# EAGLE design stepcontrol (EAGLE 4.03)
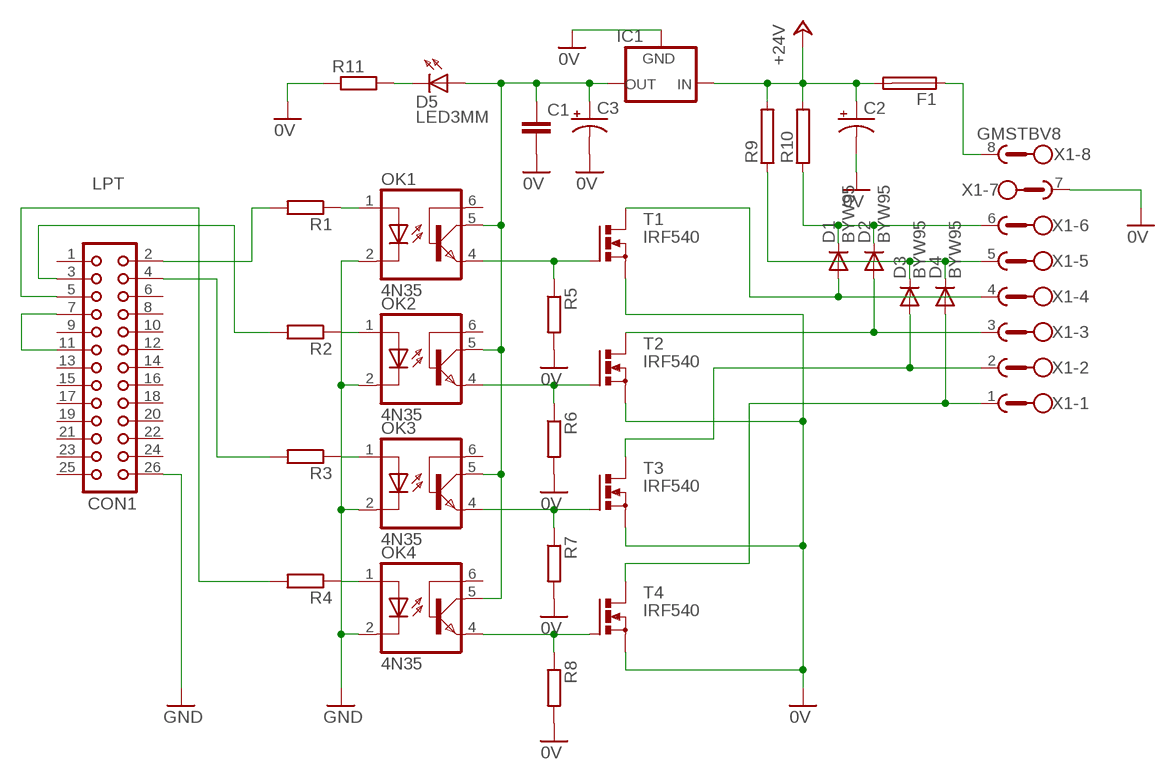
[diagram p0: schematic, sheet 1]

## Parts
C1  C-EU025-025X050  [C025-025X050]
C2  CPOL-USTAP5-50  [TAP5-50]
C3  CPOL-USTAP5-60  [TAP5-60]
CON1  CON26  [CON26]
D1  BYW95  [SOD64-10]
D2  BYW95  [SOD64-10]
D3  BYW95  [SOD64-10]
D4  BYW95  [SOD64-10]
D5  LED3MM  [LED3MM]
F1  GSH15  [GSH15]
IC1  78XXL  [78XXL]
OK1  4N35  [DIL06]
OK2  4N35  [DIL06]
OK3  4N35  [DIL06]
OK4  4N35  [DIL06]
R1  R-EU_0207/12  [0207/12]
R2  R-EU_0207/12  [0207/12]
R3  R-EU_0207/12  [0207/12]
R4  R-EU_0207/12  [0207/12]
R5  R-EU_0207/12  [0207/12]
R6  R-EU_0207/12  [0207/12]
R7  R-EU_0207/12  [0207/12]
R8  R-EU_0207/12  [0207/12]
R9  RKH214-8  [KH214-8]
R10  RKH214-8  [KH214-8]
R11  R-EU_0207/12  [0207/12]
T1  IRF540  [TO220BV]
T2  IRF540  [TO220BV]
T3  IRF540  [TO220BV]
T4  IRF540  [TO220BV]
X1  GMSTBV8  [GMSTBV8]

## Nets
0V [alimentazione]: C1.1 C2.- C3.- IC1.GND R5.2 R6.2 R7.2 R8.2 R11.1 T1.S T2.S T3.S T4.S X1.7
+24V [alimentazione]: C2.+ F1.2 IC1.IN R9.2 R10.2
GND [logic]: CON1.26 OK1.2(C) OK2.2(C) OK3.2(C) OK4.2(C)
N$1: OK4.1(A) R4.1
N$2: OK3.1(A) R3.1
N$3: OK2.1(A) R2.1
N$4: OK1.1(A) R1.1
N$5 [alimentazione]: F1.1 X1.8
N$6 [alimentazione]: D5.K(C) R11.2
N$7 [alimentazione]: D1.C D2.C R10.1 X1.6
N$8 [alimentazione]: D3.C D4.C R9.1 X1.5
N$9 [alimentazione]: D1.A T1.D X1.4
N$10 [logic]: CON1.2 R1.2
N$11 [alimentazione]: D3.A T3.D X1.2
N$12 [alimentazione]: D4.A T4.D X1.1
N$13 [logic]: CON1.3 R2.2
N$14 [alimentazione]: D2.A T2.D X1.3
N$15 [logic]: CON1.4 R3.2
N$16 [logic]: CON1.5 R4.2
N$18 [alimentazione]: OK4.4(EMI) R8.1 T4.G
N$20 [alimentazione]: OK3.4(EMI) R7.1 T3.G
N$22 [alimentazione]: OK2.4(EMI) R6.1 T2.G
N$24 [alimentazione]: OK1.4(EMI) R5.1 T1.G
N$26 [alimentazione]: C1.2 C3.+ D5.A IC1.OUT OK1.5(COL) OK2.5(COL) OK3.5(COL) OK4.5(COL)
N$27 [logic]: CON1.7 CON1.11
Unconnected: CON1.1 CON1.6 CON1.8 CON1.9 CON1.10 CON1.12 CON1.13 CON1.14 CON1.15 CON1.16 CON1.17 CON1.18 CON1.19 CON1.20 CON1.21 CON1.22 CON1.23 CON1.24 CON1.25 OK1.6(BAS) OK2.6(BAS) OK3.6(BAS) OK4.6(BAS)

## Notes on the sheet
- LPT

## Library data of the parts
C1 = rcl:C-EU: CAPACITOR, European symbol
C2 C3 = rcl:CPOL-US: POLARIZED CAPACITOR, American symbol
CON1 = con-harting:CON26: CONNECTOR
D1-D4 = diode:BYW95: DIODE
D5 = led:LED3MM: LED
F1 = fuse:GSH15: FUSE HOLDER
IC1 = v-reg:78XXL: VOLTAGE REGULATOR
OK1-OK4 = optocoupler:4N35: MOTOROLA OPTO COUPLER
R1-R8 R11 = rcl:R-EU_: RESISTOR, European symbol
R9 R10 = resistor-power:R: Power Resitor
T1-T4 = transistor-power:IRF540: N-CHANNEL MOS FET
X1 = con-phoenix-508:GMSTBV8: PHOENIX

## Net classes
1 alimentazione: width 1.016 mm
2 logic: width 0.635 mm

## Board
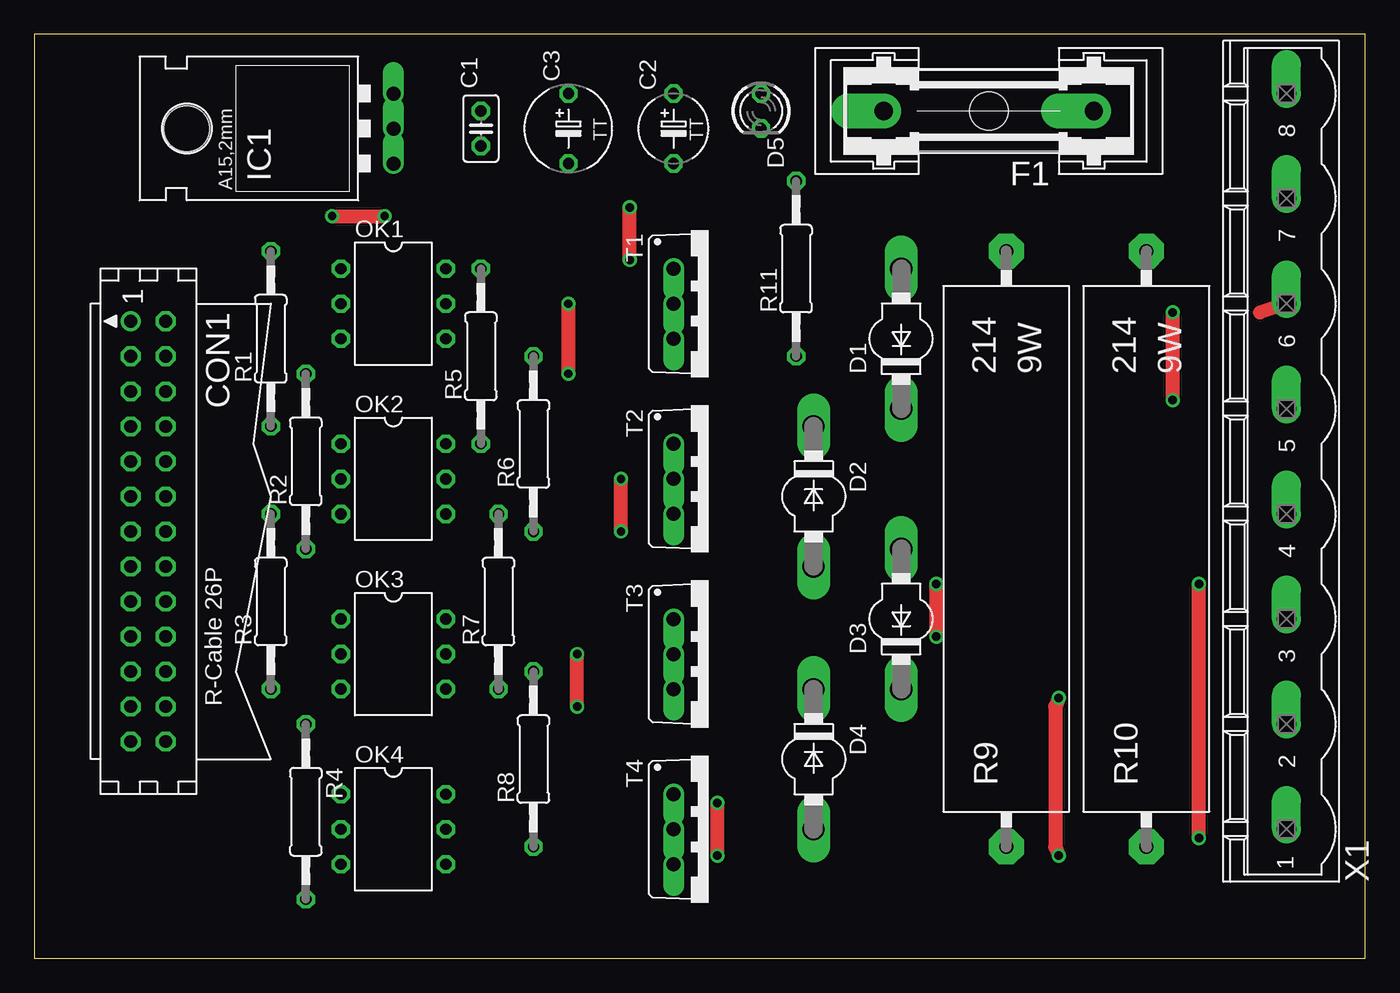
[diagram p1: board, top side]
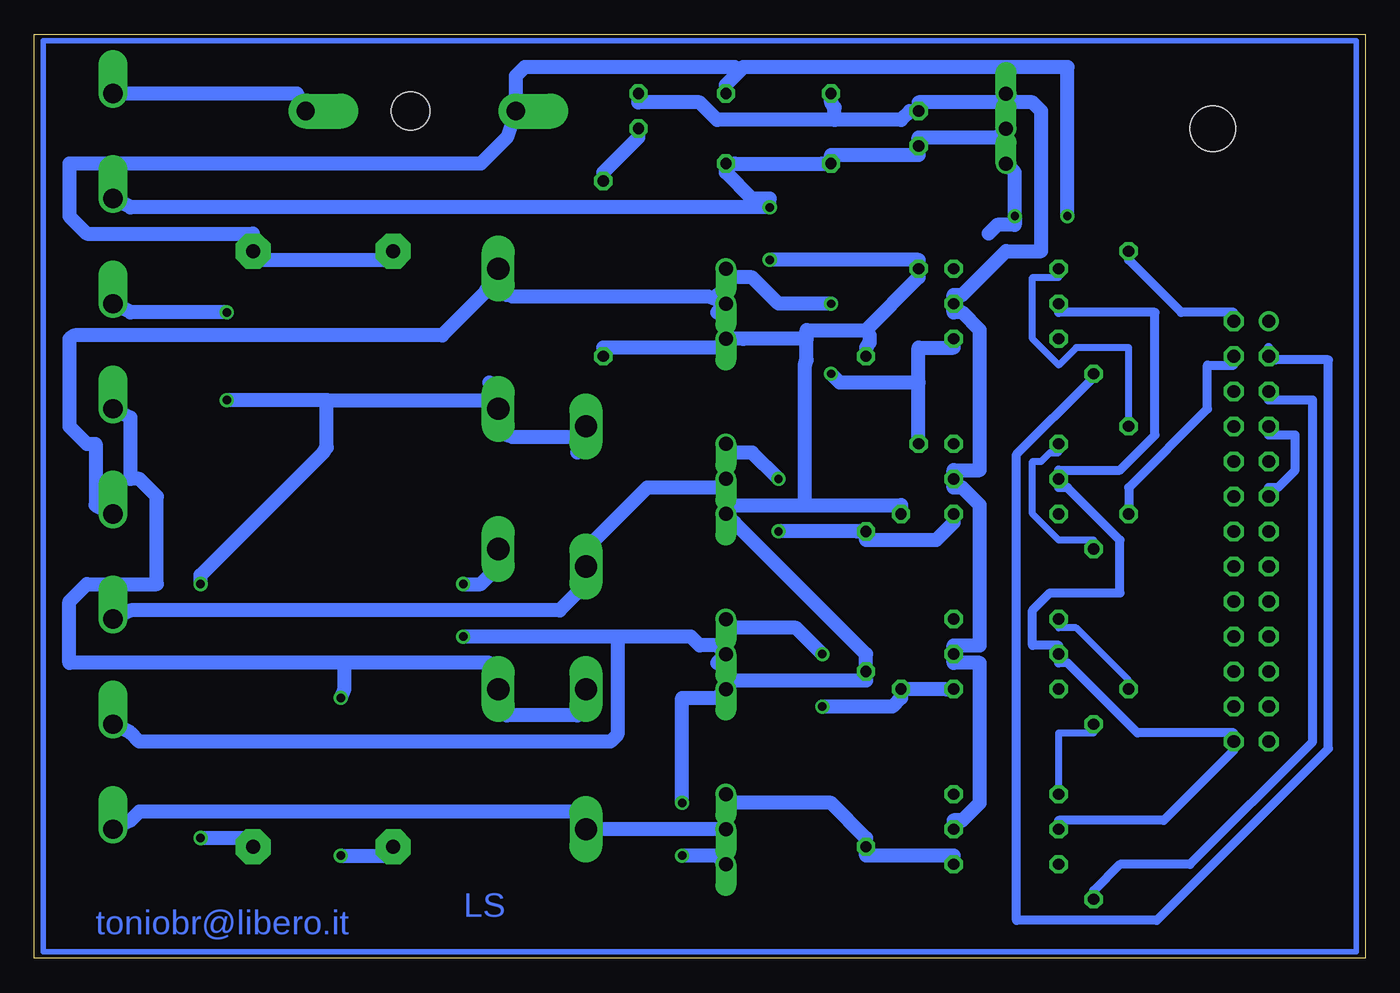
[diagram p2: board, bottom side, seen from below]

Size 96.5 x 66.98 mm. Coordinates in mm from the lower left corner, seen from the top.
Outline: 0,0 96.5,0 96.5,66.98 0,66.98 0,0
Copper layers used: Top, Bottom
tRestrict: area 4.4,11.9 to 12.1,50; area 31.1,56.4 to 56.5,64; area 56.5,55.1 to 81.9,65.2; area 7,55.1 to 23.5,65.2; area 23.5,55.1 to 31.1,65.2; area 15.9,3 to 37.5,52.5; area 54,6.8 to 60.3,56.4; area 61.6,15.7 to 64.1,55.1

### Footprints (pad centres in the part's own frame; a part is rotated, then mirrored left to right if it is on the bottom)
C025-025X050 = drill 0.813 octagon: 1 -1.27,0; 2 1.27,0
TAP5-50 = drill 0.813 octagon: + 2.54,0; - -2.54,0
TAP5-60 = drill 0.813 octagon: + 2.54,0; - -2.54,0
CON26 = drill 0.914 round: 1 -15.24,-1.27 | drill 0.914 octagon: 2 -15.24,1.27; 3 -12.7,-1.27; 4 -12.7,1.27; 5 -10.16,-1.27; 6 -10.16,1.27; 7 -7.62,-1.27; 8 -7.62,1.27; 9 -5.08,-1.27; 10 -5.08,1.27; 11 -2.54,-1.27; 12 -2.54,1.27; 13 0,-1.27; 14 0,1.27; 15 2.54,-1.27; 16 2.54,1.27; 17 5.08,-1.27; 18 5.08,1.27; 19 7.62,-1.27; 20 7.62,1.27; 21 10.16,-1.27; 22 10.16,1.27; 23 12.7,-1.27; 24 12.7,1.27; 25 15.24,-1.27; 26 15.24,1.27
SOD64-10 = drill 1.6 long: A 5.08,0; C -5.08,0
LED3MM = drill 0.813 octagon: A -1.27,0; K 1.27,0
GSH15 = drill 1.321 pad 2.54 offset: 1 -7.62,0; 2 7.62,0 | hole 2.794: 0,0
78XXL = drill 1.016 offset: GND 0,-3.81; IN -2.54,-3.81; OUT 2.54,-3.81 | hole 3.302: 0,11.176
DIL06 = drill 0.813 octagon: 1 -2.54,-3.81; 2 0,-3.81; 3 2.54,-3.81; 4 2.54,3.81; 5 0,3.81; 6 -2.54,3.81
0207/12 = drill 0.813 octagon: 1 -6.35,0; 2 6.35,0
KH214-8 = drill 1.016 pad 2.54 octagon: 1 -21.59,0; 2 21.59,0
TO220BV = drill 1.016 offset: D 0,-2.54; G -2.54,-2.54; S 2.54,-2.54
GMSTBV8 = drill 1.397 offset: 1 -26.67,0; 2 -19.05,0; 3 -11.43,0; 4 -3.81,0; 5 3.81,0; 6 11.43,0; 7 19.05,0; 8 26.67,0

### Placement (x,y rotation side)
C1  32.38,60.16 90 top
C2  46.35,60.16 90 top
C3  38.73,60.16 90 top
CON1  8.25,30.95 270 top
D1  62.86,44.92 90 top
D2  56.51,33.49 270 top
D3  62.86,24.6 90 top
D4  56.51,14.44 270 top
D5  52.7,61.43 270 top
F1  69.21,61.43 180 top
IC1  22.22,60.16 90 top
OK1  26.03,47.46 270 top
OK2  26.03,34.76 270 top
OK3  26.03,22.06 270 top
OK4  26.03,9.36 270 top
R1  17.14,44.92 90 top
R2  19.68,36.03 90 top
R3  17.14,25.87 90 top
R4  19.68,10.63 270 top
R5  32.38,43.65 90 top
R6  36.19,37.3 90 top
R7  33.65,25.87 90 top
R8  36.19,14.44 90 top
R9  70.48,29.68 90 top
R10  80.64,29.68 90 top
R11  55.24,50 90 top
T1  48.89,47.46 270 top
T2  48.89,34.76 270 top
T3  48.89,22.06 270 top
T4  48.89,9.36 270 top
X1  90.8,36.03 90 top

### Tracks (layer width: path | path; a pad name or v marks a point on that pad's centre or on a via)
0V  (via drill 0.61)
  Top 1.016: v43.17,50.63 v43.17,54.45 | v49.52,7.46 v49.52,11.27
  Bottom 1.016: 40.63,32.86 33.65,32.86 R7.2 | R6.2 36.19,44.29 35.94,44.67 35.94,45.17 36.19,45.55 | 36.19,45.55 32.38,49.37 R5.2 32.38,50.63 v43.17,50.63 | 36.19,45.55 40.51,45.55 40.51,44.92 | IC1.GND 26.66,59.52 32.38,59.52 C1.1 32.38,58.26 38.73,58.26 C3.- 39.37,57.62 45.71,57.62 C2.- 46.35,56.99 44.45,55.08 43.17,55.08 v43.17,54.45 89.53,54.45 X1.7 | 40.63,32.86 40.63,43.02 40.51,43.4 40.51,44.92 | v49.52,7.46 46.98,7.46 T4.S | v49.52,11.27 49.52,18.88 46.98,18.88 T3.S 45.71,20.16 36.19,20.16 R8.2 36.19,22.06 45.71,31.59 T2.S 45.71,32.86 40.63,32.86 | R11.1 55.24,44.29 46.98,44.29 T1.S 45.08,44.92 40.51,44.92
+24V  (via drill 0.61)
  Top 1.016: v21.58,53.81 v25.39,53.81
  Bottom 1.016: v21.58,53.81 21.58,64.6 45.08,64.6 45.4,64.29 | IC1.IN 25.39,56.99 v25.39,53.81 25.39,53.18 26.66,53.18 27.3,52.54 | R9.2 71.12,50.63 80.01,50.63 R10.2 80.64,52.54 92.71,52.54 93.98,53.81 93.98,57.62 64.13,57.62 62.23,59.52 F1.2 61.59,63.97 60.95,64.6 45.71,64.6 45.4,64.29 | 45.4,64.29 46.35,63.34 C2.+
GND
  Bottom 0.635: OK1.2 22.22,46.83 15.24,46.83 15.24,37.94 17.77,35.4 22.22,35.4 OK2.2 22.22,34.12 21.58,34.12 17.77,30.31 17.77,26.51 22.85,26.51 24.12,25.23 24.12,22.7 22.22,22.7 OK3.2 22.22,21.43 21.58,21.43 16.5,16.34 9.52,16.34 CON1.26 9.52,15.07 14.6,10 22.22,10 OK4.2
N$1
  Bottom 0.508: OK4.1 22.22,16.34 19.68,16.34 R4.1
N$2
  Bottom 0.508: R3.1 17.14,20.16 20.95,23.97 22.22,23.97 OK3.1
N$3
  Bottom 0.508: R2.1 19.68,30.31 22.22,30.31 24.12,32.22 24.12,36.03 23.49,36.03 22.85,36.66 22.22,36.66 OK2.1
N$4
  Bottom 0.508: R1.1 17.14,44.29 20.95,44.29 22.22,43.02 24.12,44.92 24.12,49.37 22.22,49.37 OK1.1
N$5
  Bottom 1.016: X1.8 88.9,62.7 77.47,62.7 F1.1
N$6
  Bottom 1.016: R11.2 55.24,56.99 52.7,59.52 D5.K
N$7  (via drill 0.61)
  Top 1.016: X1.6 88.9,46.83 | v82.55,40.48 v82.55,46.83 | v84.45,8.73 v84.45,27.14
  Bottom 1.016: D1.C 63.49,41.74 | D2.C 57.14,37.94 | D1.C 62.23,37.94 61.84,37.81 57.53,37.81 D2.C | 75.31,40.48 63.49,40.48 D1.C | 75.31,40.48 v82.55,40.48 | D2.C 57.14,36.66 | v82.55,46.83 89.53,46.83 X1.6 | v84.45,27.14 84.45,27.77 75.56,36.66 75.31,37.05 75.31,40.48 | v84.45,8.73 81.28,8.73 R10.1
N$8  (via drill 0.61)
  Top 1.016: v74.29,7.46 74.04,8.09 74.04,18.25 v74.29,18.88
  Bottom 1.016: 74.04,21.43 63.49,21.43 D3.C | 74.04,21.43 93.98,21.43 93.98,25.87 92.71,27.14 87.62,27.14 87.62,33.49 88.9,34.76 89.53,34.76 89.53,39.2 X1.5 | D4.C 57.14,17.62 62.23,17.62 D3.C | D3.C 63.49,18.88 | v74.29,7.46 71.12,7.46 R9.1 | v74.29,18.88 74.04,19.52 74.04,21.43
N$9
  Bottom 1.016: T1.D 46.98,48.1 | X1.4 92.07,32.86 92.07,37.3 92.71,37.3 93.98,38.57 93.98,44.92 93.59,45.17 66.92,45.17 63.88,48.22 D1.A 62.23,48.1 61.84,47.97 47.62,47.97 T1.D | 46.98,46.83 T1.D
N$10
  Bottom 0.635: R1.2 17.14,50.63 13.33,46.83 9.52,46.83 CON1.2
N$11  (via drill 0.61)
  Top 1.016: v65.4,23.33 v65.4,27.14
  Bottom 1.016: 46.98,21.43 T3.D 46.98,22.7 48.25,22.7 48.89,23.33 54.22,23.33 | X1.2 89.53,16.34 88.9,15.71 54.73,15.71 54.22,16.22 54.22,23.33 | v65.4,27.14 64.13,27.14 63.49,27.77 D3.A | 54.22,23.33 v65.4,23.33
N$12
  Bottom 1.016: T4.D 47.62,9.36 55.88,9.36 D4.A 57.14,10.63 88.9,10.63 89.53,10 X1.1
N$13
  Bottom 0.635: 6.98,44.29 CON1.3 6.47,43.4 2.66,43.4 2.66,15.2 15.11,2.76 25.27,2.76 25.27,36.54 19.93,41.87 R2.2
N$14
  Bottom 1.016: T2.D 46.98,34.12 52.06,34.12 55.88,30.31 D2.A 57.14,26.51 58.41,25.23 89.53,25.23 X1.3
N$15
  Bottom 0.635: R3.2 17.14,34.12 11.43,39.84 11.43,43.02 9.52,43.02 CON1.4
N$16
  Bottom 0.635: R4.2 19.68,4.91 17.77,6.82 12.7,6.82 3.8,15.71 3.8,40.48 6.98,40.48 CON1.5
N$17
  Bottom 0.406: 0.63,0.47 95.88,0.47 95.88,66.51 0.63,66.51 0.63,0.47
N$18
  Bottom 1.016: OK4.4 29.84,7.46 36.19,7.46 R8.1 36.19,8.73 38.73,11.27 45.71,11.27 T4.G
N$20  (via drill 0.61)
  Top 1.016: v39.37,18.25 v39.37,22.06
  Bottom 1.016: OK3.4 30.47,19.52 33.02,19.52 R7.1 33.65,18.88 34.28,18.25 v39.37,18.25 | v39.37,22.06 41.27,23.97 45.71,23.97 T3.G
N$22  (via drill 0.61)
  Top 1.016: v42.54,30.95 v42.54,34.76
  Bottom 1.016: OK2.4 29.84,31.59 31.11,30.31 36.19,30.31 R6.1 36.82,30.95 v42.54,30.95 | v42.54,34.76 44.45,36.66 45.71,36.66 T2.G
N$24  (via drill 0.61)
  Top 1.016: v38.73,42.38 v38.73,47.46
  Bottom 1.016: 32.38,41.74 32.38,44.29 29.84,44.29 OK1.4 | R5.1 32.38,41.74 | v38.73,47.46 42.54,47.46 44.45,49.37 45.71,49.37 T1.G | v38.73,42.38 38.09,41.74 32.38,41.74
N$26
  Bottom 1.016: C3.+ 38.73,62.07 38.48,61.68 38.48,60.79 | 38.48,60.79 33.65,60.79 33.02,61.43 C1.2 32.38,62.07 26.66,62.07 IC1.OUT 25.39,62.07 24.12,62.07 23.49,61.43 23.49,51.27 26.03,51.27 29.2,48.1 29.84,48.1 OK1.5 29.84,46.83 29.2,46.83 27.93,45.55 27.93,35.4 29.84,35.4 OK2.5 29.84,34.12 29.2,34.12 27.93,32.86 27.93,22.7 29.84,22.7 OK3.5 29.84,21.43 27.93,21.43 27.93,11.27 29.2,10 29.84,10 OK4.5 | D5.A 52.7,62.07 48.25,62.07 46.98,60.79 38.48,60.79
N$27
  Bottom 0.635: CON1.11 6.98,34.12 6.35,34.12 5.07,35.4 5.07,37.94 6.98,37.94 CON1.7

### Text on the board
Bottom: LS | toniobr@libero.it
